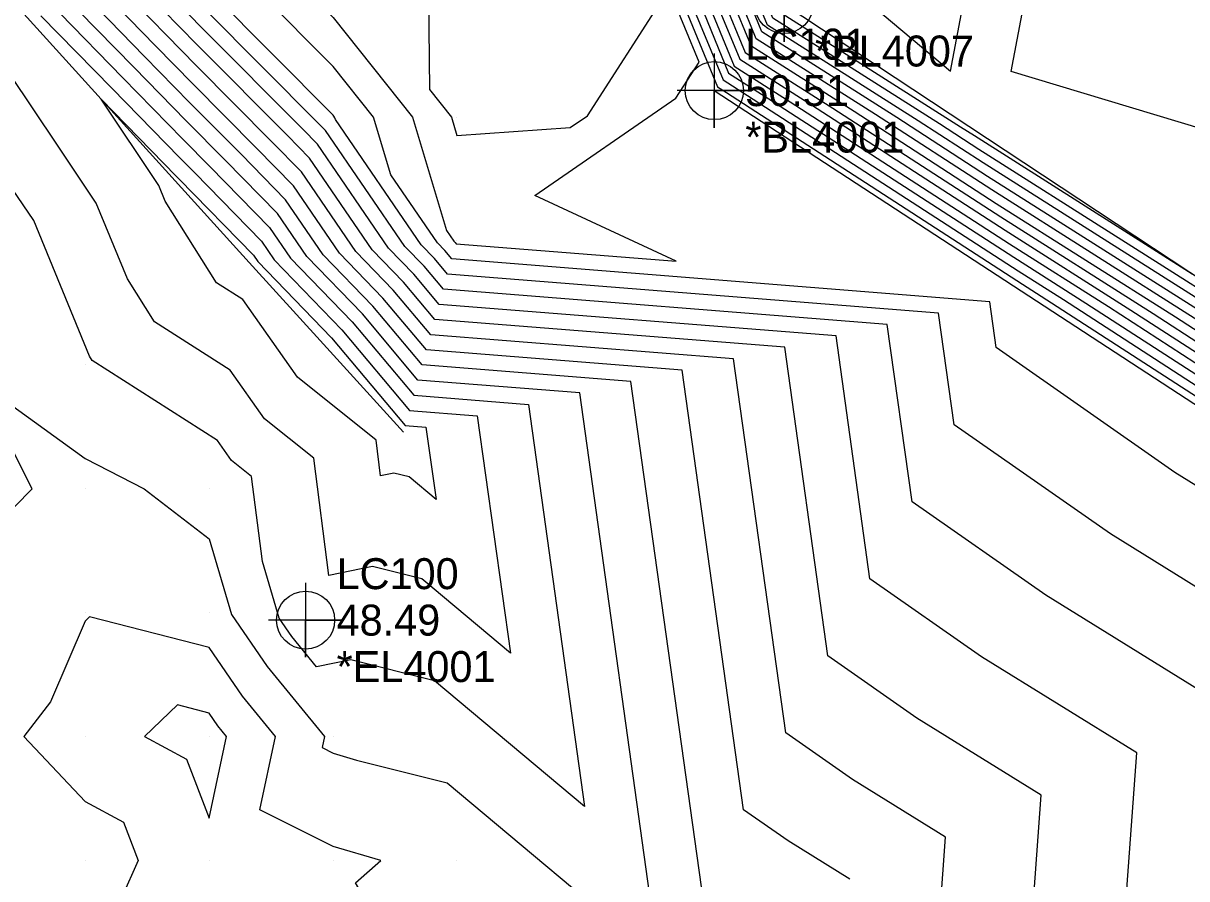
# Model space of a CAD drawing. Extents: x 2188792 to 2191981, y 386090 to 389710.
# Drawn here: x 2189865.1 to 2189959, y 387528.7 to 387597.7 of the extents above; entities that cross this region are included whole.
import ezdxf

# ---------------------------------------------------------------- set-up
doc = ezdxf.new("R2010")
doc.units = 0
for name, color, linetype in [('DTM Contours Major', 7, 'Continuous'), ('DTM Contours Minor', 7, 'Continuous'), ('Exist DTM Breakline', 7, 'Continuous'), ('Exist DTM Breakline Cogo Comment', 7, 'Continuous'), ('Exist DTM Breakline Cogo Elevation', 7, 'Continuous'), ('Exist DTM Breakline Cogo Number', 7, 'Continuous'), ('Exist DTM Breakline Cogo Point CELL', 7, 'Continuous'), ('Exist DTM Breakline Underwater', 7, 'Continuous'), ('Exist DTM Breakline Underwater Cogo Comment', 7, 'Continuous'), ('Exist DTM Breakline Underwater Cogo Point CELL', 7, 'Continuous'), ('Exist DTM QL2 LIDAR Elevation Point', 7, 'Continuous'), ('Exist DTM Regular Point Underwater CELL', 7, 'Continuous'), ('Exist DTM Regular Point Underwater Cogo Comment', 7, 'Continuous'), ('Exist DTM Regular Point Underwater Cogo Elevation', 7, 'Continuous'), ('Exist DTM Regular Point Underwater Cogo Number', 7, 'Continuous'), ('PH Exist DTM Breakline', 7, 'Continuous')]:
    doc.layers.add(name, color=color, linetype=linetype)

msp = doc.modelspace()

# ---------------------------------------------------------------- linework, layer by layer
at = {"layer": 'DTM Contours Major'}
for points in [[(2189966.148, 387587.407), (2189944.825, 387593.838), (2189950.126, 387621.819), (2189938.989, 387630.402), (2189937.941, 387633.851), (2189942.783, 387638.383), (2189942.963, 387642.134), (2189946.851, 387646.076), (2189958.651, 387638.597), (2189962.844, 387642.767)], [(2189919.447, 387599.987), (2189922.017, 387593.714), (2189925.276, 387591.644), (2189945.038, 387578.841), (2189950.861, 387575.147), (2189963.225, 387567.139)], [(2189924.257, 387596.481), (2189922.974, 387599.614)], [(2189893.297, 387574.908), (2189889.307, 387579.041), (2189886.258, 387583.491), (2189882.676, 387587.159), (2189878.506, 387591.346), (2189874.895, 387595.047), (2189871.087, 387598.948)], [(2189962.671, 387542.238), (2189947.626, 387551.564), (2189936.822, 387559.113), (2189934.825, 387573.417), (2189899.007, 387576.264), (2189897.45, 387578.115), (2189895.896, 387579.724), (2189889.48, 387589.088), (2189888.904, 387589.678), (2189879.846, 387598.775)], [(2189959.878, 387573.749), (2189943.268, 387584.286), (2189933.871, 387590.374), (2189924.257, 387596.481)], [(2189919.838, 387528.02), (2189914.142, 387568.816), (2189897.296, 387570.155), (2189893.297, 387574.908)], [(2189882.802, 387543.423), (2189880.096, 387547.344), (2189870.436, 387549.816), (2189870.095, 387549.488), (2189867.285, 387542.966), (2189865.146, 387540.156), (2189870.095, 387534.925), (2189873.194, 387533.254), (2189874.381, 387530.155), (2189873.062, 387527.188), (2189869.925, 387514.816), (2189874.721, 387509.85), (2189887.333, 387512.918), (2189890.097, 387513.115), (2189896.771, 387513.48), (2189896.689, 387520.154), (2189891.906, 387528.347), (2189893.954, 387530.155), (2189890.097, 387531.285), (2189884.185, 387534.244), (2189885.456, 387540.156), (2189882.802, 387543.423)]]:
    msp.add_lwpolyline(points, dxfattribs=at)
at = {"layer": 'DTM Contours Minor'}
for points in [[(2189963.485, 387573.19), (2189942.561, 387586.464), (2189937.309, 387589.866), (2189925.154, 387597.587), (2189924.384, 387599.464), (2189922.07, 387611.491), (2189921.786, 387611.689), (2189919.163, 387614.038), (2189924.613, 387614.381), (2189929.182, 387614.837), (2189933.422, 387611.277), (2189935.186, 387620.584), (2189932.358, 387622.763), (2189930.107, 387630.168), (2189940.503, 387639.899), (2189940.891, 387647.952), (2189949.237, 387656.416), (2189952.378, 387654.425), (2189960.837, 387662.834)], [(2189965.289, 387572.91), (2189942.207, 387587.553), (2189939.028, 387589.612), (2189925.602, 387598.14), (2189925.09, 387599.39), (2189923.218, 387609.115), (2189928.283, 387609.62), (2189936.675, 387602.572), (2189940.166, 387620.996), (2189934.568, 387625.31), (2189932.719, 387631.395), (2189941.263, 387639.393), (2189941.582, 387646.012), (2189948.441, 387652.969), (2189954.469, 387649.149), (2189961.506, 387656.145)], [(2189959.426, 387577.494), (2189941.853, 387588.642), (2189940.747, 387589.358), (2189926.05, 387598.694), (2189925.795, 387599.315), (2189924.864, 387604.152), (2189927.383, 387604.403), (2189939.928, 387593.868), (2189945.146, 387621.407), (2189936.778, 387627.856), (2189935.33, 387632.623), (2189942.023, 387638.888), (2189942.272, 387644.073), (2189947.646, 387649.523), (2189956.56, 387643.873), (2189962.175, 387649.456)], [(2189917.331, 387600.211), (2189917.106, 387601.385), (2189910.271, 387606.158), (2189909.507, 387606.842), (2189908.618, 387607.638), (2189902.169, 387612.234), (2189900.098, 387613.911), (2189895.191, 387615.07), (2189890.976, 387610.163), (2189890.097, 387607.122), (2189888.793, 387601.466), (2189888.138, 387600.162), (2189890.097, 387598.184), (2189896.512, 387590.161), (2189899.253, 387581.005), (2189899.85, 387580.134), (2189899.942, 387580.039), (2189900.034, 387579.929), (2189917.797, 387578.518), (2189906.372, 387583.826), (2189917.764, 387591.68), (2189919.634, 387594.591), (2189917.331, 387600.211)], [(2189916.626, 387600.286), (2189916.609, 387600.374), (2189909.119, 387605.605), (2189908.809, 387605.882), (2189908.449, 387606.205), (2189901.262, 387611.327), (2189900.098, 387612.27), (2189897.34, 387612.921), (2189894.971, 387610.163), (2189892.887, 387602.951), (2189897.778, 387602.295), (2189897.88, 387592.379), (2189899.654, 387590.161), (2189900.098, 387588.676), (2189909.248, 387589.309), (2189910.637, 387590.267), (2189916.799, 387599.863), (2189916.626, 387600.286)], [(2189970.388, 387545.636), (2189952.829, 387556.521), (2189940.219, 387565.332), (2189938.962, 387574.337), (2189899.349, 387577.486), (2189898.28, 387578.756), (2189897.214, 387579.861), (2189890.285, 387589.972), (2189890.229, 387590.161), (2189890.097, 387590.326), (2189880.357, 387600.162)], [(2189978.106, 387549.034), (2189958.031, 387561.478), (2189943.616, 387571.55), (2189943.098, 387575.258), (2189899.691, 387578.708), (2189899.111, 387579.398), (2189898.532, 387579.997), (2189894.769, 387585.489), (2189893.371, 387590.161), (2189890.097, 387594.255), (2189884.248, 387600.162)], [(2189918.037, 387600.136), (2189921.121, 387592.607), (2189921.838, 387592.152), (2189945.745, 387576.663), (2189947.255, 387575.706), (2189962.434, 387565.874)], [(2189918.742, 387600.062), (2189921.569, 387593.161), (2189923.557, 387591.898), (2189945.391, 387577.752), (2189949.058, 387575.426), (2189962.83, 387566.507)], [(2189920.153, 387599.912), (2189922.465, 387594.267), (2189926.995, 387591.39), (2189944.684, 387579.93), (2189952.665, 387574.867), (2189963.621, 387567.771)], [(2189920.858, 387599.838), (2189922.913, 387594.821), (2189928.714, 387591.136), (2189944.33, 387581.019), (2189954.468, 387574.588), (2189964.016, 387568.404)], [(2189921.563, 387599.763), (2189923.361, 387595.374), (2189930.433, 387590.882), (2189943.976, 387582.108), (2189956.272, 387574.308), (2189964.411, 387569.036)], [(2189922.269, 387599.688), (2189923.809, 387595.927), (2189932.152, 387590.628), (2189943.622, 387583.197), (2189958.075, 387574.028), (2189964.807, 387569.668)], [(2189881.91, 387562.454), (2189880.787, 387564.044), (2189870.667, 387570.515), (2189870.444, 387570.871), (2189865.941, 387581.802), (2189864.236, 387584.354), (2189862.221, 387587.37), (2189859.021, 387594.837), (2189858.946, 387599.018)], [(2189892.466, 387574.267), (2189887.989, 387578.905), (2189885.614, 387582.372), (2189881.43, 387586.655), (2189878.238, 387589.86), (2189874.018, 387594.184), (2189869.568, 387598.744)], [(2189894.127, 387575.55), (2189890.625, 387579.178), (2189886.902, 387584.611), (2189883.921, 387587.662), (2189878.774, 387592.832), (2189875.771, 387595.909), (2189872.605, 387599.153)], [(2189894.958, 387576.191), (2189891.943, 387579.315), (2189887.547, 387585.73), (2189885.167, 387588.166), (2189879.042, 387594.318), (2189876.648, 387596.771), (2189874.124, 387599.357)], [(2189965.773, 387496.586), (2189945.388, 387509.305), (2189945.822, 387515.801), (2189947.237, 387535.442), (2189937.221, 387541.65), (2189930.029, 387546.676), (2189926.552, 387571.576), (2189898.323, 387573.82), (2189895.789, 387576.832), (2189893.261, 387579.451), (2189888.191, 387586.849), (2189886.412, 387588.67), (2189879.31, 387595.804), (2189877.525, 387597.633), (2189875.642, 387599.562)], [(2189961.682, 387573.469), (2189942.914, 387585.375), (2189935.59, 387590.12), (2189924.705, 387597.034), (2189923.679, 387599.539)], [(2189884.565, 387565.817), (2189881.797, 387569.733), (2189875.682, 387573.644), (2189873.5, 387577.115), (2189870.986, 387583.219), (2189867.809, 387587.973), (2189864.055, 387593.591), (2189862.696, 387596.762), (2189862.664, 387598.538)], [(2189866.531, 387598.335), (2189872.265, 387592.46), (2189877.703, 387586.888), (2189878.939, 387585.647), (2189884.325, 387580.133), (2189885.354, 387578.632), (2189890.805, 387572.984), (2189896.269, 387566.489), (2189901.732, 387566.055), (2189904.407, 387546.895), (2189897.258, 387552.881), (2189893.271, 387553.887), (2189889.754, 387553.153), (2189888.547, 387562.622), (2189884.565, 387565.817)], [(2189868.049, 387598.539), (2189873.141, 387593.322), (2189877.971, 387588.374), (2189880.184, 387586.151), (2189884.969, 387581.252), (2189886.671, 387578.768), (2189891.635, 387573.626), (2189896.611, 387567.711), (2189905.868, 387566.975), (2189910.402, 387534.506), (2189898.286, 387544.65), (2189891.53, 387546.355), (2189888.773, 387545.78), (2189886.783, 387548.23), (2189885.753, 387549.722), (2189884.4, 387554.301), (2189883.526, 387561.158), (2189881.91, 387562.454)], [(2189970.196, 387503.396), (2189953.216, 387513.992), (2189953.871, 387523.813), (2189954.954, 387538.84), (2189942.423, 387546.607), (2189933.426, 387552.894), (2189930.688, 387572.497), (2189898.665, 387575.042), (2189896.619, 387577.474), (2189894.578, 387579.588), (2189888.835, 387587.969), (2189887.658, 387589.174), (2189879.578, 387597.29), (2189878.402, 387598.495)], [(2189887.22, 387569.179), (2189882.808, 387575.423), (2189880.697, 387576.773), (2189876.556, 387583.36), (2189876.03, 387584.635), (2189871.382, 387591.592), (2189871.357, 387591.63), (2189871.388, 387591.598), (2189877.435, 387585.403), (2189877.693, 387585.143), (2189883.681, 387579.013), (2189884.036, 387578.495), (2189889.974, 387572.343), (2189895.927, 387565.267), (2189897.595, 387565.134), (2189898.412, 387559.284), (2189896.229, 387561.111), (2189895.011, 387561.419), (2189893.937, 387561.195), (2189893.569, 387564.086), (2189887.22, 387569.179)], [(2189961.349, 387489.775), (2189937.561, 387504.619), (2189937.772, 387507.788), (2189939.519, 387532.044), (2189932.018, 387536.694), (2189926.632, 387540.457), (2189922.415, 387570.656), (2189897.98, 387572.598), (2189894.958, 387576.191)], [(2189931.802, 387528.645), (2189926.816, 387531.737), (2189923.235, 387534.238), (2189918.278, 387569.736), (2189897.638, 387571.376), (2189894.127, 387575.55)], [(2189862.966, 387557.286), (2189865.806, 387560.158), (2189861.394, 387568.86), (2189870.095, 387562.611), (2189874.856, 387560.158), (2189880.096, 387556.119), (2189881.9, 387550.018), (2189884.793, 387545.827), (2189889.399, 387540.156), (2189889.208, 387539.267), (2189890.097, 387538.822), (2189891.984, 387538.269), (2189899.315, 387536.419), (2189916.397, 387522.118), (2189910.005, 387567.895), (2189896.954, 387568.933), (2189892.466, 387574.267)], [(2189880.812, 387541.02), (2189880.096, 387542.057), (2189877.542, 387542.71), (2189874.886, 387540.156), (2189878.271, 387538.331), (2189880.096, 387533.565), (2189881.514, 387540.156), (2189880.812, 387541.02)]]:
    msp.add_lwpolyline(points, dxfattribs=at)
at = {"layer": 'Exist DTM Breakline'}
msp.add_lwpolyline([(2189920.868, 387592.295), (2189962.123, 387565.377), (2189980.085, 387549.906), (2189986.896, 387547.677), (2189998.329, 387555.668), (2190012.456, 387589.752), (2190048.075, 387631.731), (2190076.07, 387674.573), (2190074.562, 387678.377), (2190070.092, 387679.666), (2190029.766, 387708.101), (2190010.729, 387719.436), (2190038.07, 387742.576)], dxfattribs=at)
at = {"layer": 'Exist DTM Breakline Cogo Point CELL'}
msp.add_lwpolyline([(2189920.868, 387595.295), (2189920.868, 387589.295), (2189920.868, 387592.295), (2189923.868, 387592.295), (2189917.868, 387592.295)], dxfattribs=at)
msp.add_circle((2189920.868, 387592.295), 2.344, dxfattribs=at)
at = {"layer": 'Exist DTM Breakline Underwater'}
msp.add_lwpolyline([(2190044.846, 387633.972), (2190011.332, 387590.769), (2189992.696, 387560.383), (2189987.062, 387555.03), (2189983.211, 387554.531), (2189966.698, 387572.692), (2189926.493, 387599.241)], dxfattribs=at)
at = {"layer": 'Exist DTM Breakline Underwater Cogo Point CELL'}
msp.add_lwpolyline([(2189926.493, 387602.241), (2189926.493, 387596.241), (2189926.493, 387599.241), (2189929.493, 387599.241), (2189923.493, 387599.241)], dxfattribs=at)
msp.add_circle((2189926.493, 387599.241), 2.344, dxfattribs=at)
at = {"layer": 'Exist DTM QL2 LIDAR Elevation Point'}
for p, q in [((2189890.097, 387590.161), (2189890.097, 387590.161)), ((2189900.098, 387590.161), (2189900.098, 387590.161)), ((2189910.099, 387590.161), (2189910.099, 387590.161)), ((2189900.098, 387580.16), (2189900.098, 387580.16)), ((2189870.095, 387570.159), (2189870.095, 387570.159)), ((2189870.095, 387560.158), (2189870.095, 387560.158)), ((2189880.096, 387560.158), (2189880.096, 387560.158)), ((2189870.095, 387550.157), (2189870.095, 387550.157)), ((2189880.096, 387550.157), (2189880.096, 387550.157)), ((2189870.095, 387540.156), (2189870.095, 387540.156)), ((2189880.096, 387540.156), (2189880.096, 387540.156)), ((2189890.097, 387540.156), (2189890.097, 387540.156)), ((2189870.095, 387530.155), (2189870.095, 387530.155)), ((2189880.096, 387530.155), (2189880.096, 387530.155)), ((2189890.097, 387530.155), (2189890.097, 387530.155)), ((2189900.098, 387530.155), (2189900.098, 387530.155))]:
    msp.add_line(p, q, dxfattribs=at)
at = {"layer": 'Exist DTM Regular Point Underwater CELL'}
msp.add_lwpolyline([(2189887.884, 387552.559), (2189887.884, 387546.559), (2189887.884, 387549.559), (2189890.884, 387549.559), (2189884.884, 387549.559)], dxfattribs=at)
msp.add_circle((2189887.884, 387549.559), 2.344, dxfattribs=at)
at = {"layer": 'PH Exist DTM Breakline'}
msp.add_lwpolyline([(2189830.091, 387640.166), (2189834.403, 387634.348), (2189838.715, 387628.531), (2189843.027, 387622.714), (2189848.495, 387616.733), (2189853.964, 387610.752), (2189859.433, 387604.77), (2189865.41, 387598.184), (2189871.387, 387591.597), (2189877.364, 387585.01), (2189883.341, 387578.423), (2189889.318, 387571.836), (2189895.777, 387564.73)], dxfattribs=at)

# ---------------------------------------------------------------- texts
at = {"layer": 'Exist DTM Breakline Cogo Comment'}
msp.add_text('*BL4001', height=2.5, dxfattribs=at).set_placement((2189923.368, 387587.295))
at = {"layer": 'Exist DTM Breakline Cogo Elevation'}
msp.add_text('50.51', height=2.5, dxfattribs=at).set_placement((2189923.368, 387591.045))
at = {"layer": 'Exist DTM Breakline Cogo Number'}
msp.add_text('LC101', height=2.5, dxfattribs=at).set_placement((2189923.368, 387594.795))
at = {"layer": 'Exist DTM Breakline Underwater Cogo Comment'}
msp.add_text('*BL4007', height=2.5, dxfattribs=at).set_placement((2189928.993, 387594.241))
at = {"layer": 'Exist DTM Regular Point Underwater Cogo Comment'}
msp.add_text('*EL4001', height=2.5, dxfattribs=at).set_placement((2189890.384, 387544.559))
at = {"layer": 'Exist DTM Regular Point Underwater Cogo Elevation'}
msp.add_text('48.49', height=2.5, dxfattribs=at).set_placement((2189890.384, 387548.309))
at = {"layer": 'Exist DTM Regular Point Underwater Cogo Number'}
msp.add_text('LC100', height=2.5, dxfattribs=at).set_placement((2189890.384, 387552.059))

doc.saveas('drawing.dxf')
